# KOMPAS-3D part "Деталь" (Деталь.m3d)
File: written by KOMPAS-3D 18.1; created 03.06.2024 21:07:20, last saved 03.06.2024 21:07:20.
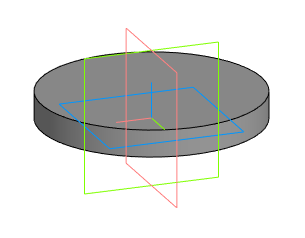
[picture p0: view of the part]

Document properties: Полное имя файла: C:\Users\root\Desktop\Новая папка\тест\Деталь.m3d

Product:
- Part/product: Деталь
    Масса: 0.414877

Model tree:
1. Эскиз:1
2. Элемент выдавливания:1
     Расстояние 1 = 10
